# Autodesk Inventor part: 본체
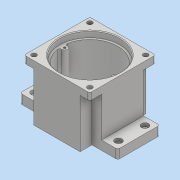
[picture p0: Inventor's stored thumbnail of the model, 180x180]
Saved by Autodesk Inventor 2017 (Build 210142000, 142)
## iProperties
Part Number: 본체
Material: 일반
Document SubType Name: Modeling
Designer: user
Density: 1 g/cm^3
Appearance: 기본값
Author: user
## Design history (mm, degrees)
sketch "스케치1"
  geometry: L1 (-70, -30)-(70, -30); L2 (70, -30)-(70, 30); L3 (70, 30)-(-70, 30); L4 (-70, 30)-(-70, -30); L5 (-70, -30)-(70, 30); L6 (70, -30)-(-70, 30); L7 (-33, -47)-(33, -47); L8 (33, -47)-(33, 47); L9 (33, 47)-(-33, 47); L10 (-33, 47)-(-33, -47); L11 (-33, -47)-(33, 47); L12 (33, -47)-(-33, 47); 1 further point
  constraints: 24 end point, 4 midpoint, 4 parallel, 2 horizontal, 2 perpendicular
  dimensions: "d0" = 66 distance of L8.end L9.end; "d1" = 60 distance of L1.end L2.end; "d2" = 140 distance of L1.start L1.end; "d3" = 94 distance between parallel lines of L9 L7
extrude "돌출1" new body sketch "스케치1" distance "d4" = 13; taper "d5" = 0 deg
sketch "스케치2"
  geometry: L1 (-33, 47)-(33, 47); L2 (33, 47)-(33, -47); L3 (33, -47)-(-33, -47); L4 (-33, -47)-(-33, 47); L5 (-33, 47)-(33, -47); L6 (33, 47)-(-33, -47); L7 (-47, -30)-(47, -30); L8 (47, -30)-(47, 30); L9 (47, 30)-(-47, 30); L10 (-47, 30)-(-47, -30); L11 (-47, -30)-(47, 30); L12 (47, -30)-(-47, 30); 3 further points
  constraints: 24 end point, 5 midpoint, 4 parallel, 2 horizontal, 2 perpendicular, 1 coincident
  dimensions: "d6" = 66 distance of L1.start L1.end; "d7" = 94 distance of L1.end L2.end; "d8" = 94 distance of L8.end L9.end; "d9" = 60 distance of L7.end L8.end
extrude "돌출2" join sketch "스케치2" distance "d10" = 57; taper "d11" = 0 deg
sketch "스케치3"
  geometry: L1 (-47, -47)-(47, -47); L2 (47, -47)-(47, 47); L3 (47, 47)-(-47, 47); L4 (-47, 47)-(-47, -47); L5 (-47, -47)-(47, 47); L6 (47, -47)-(-47, 47); 3 further points
  constraints: 12 end point, 3 midpoint, 2 parallel, 1 coincident, 1 horizontal, 1 perpendicular
  dimensions: "d12" = 94 distance of L2.end L3.end; "d13" = 94 distance of L1.end L2.end
extrude "돌출3" join sketch "스케치3" distance "d14" = 10; taper "d15" = 0 deg
sketch "스케치4"
  geometry: L1 (-40, -40)-(40, -40); L2 (40, -40)-(40, 40); L3 (40, 40)-(-40, 40); L4 (-40, 40)-(-40, -40); L5 (-40, -40)-(40, 40); L6 (40, -40)-(-40, 40); C1 r 3.5 at (40, 40); C2 r 3.5 at (-40, 40); C3 r 3.5 at (-40, -40); C4 r 3.5 at (40, -40); 1 further point
  constraints: 12 end point, 4 centre point, 3 coincident, 2 midpoint, 2 parallel, 1 horizontal, 1 perpendicular
  dimensions: "d16" = 80 distance of L2.end L3.end; "d17" = 80 distance of L1.end L2.end; "d18" = 7 diameter of C1; "d19" = 7 diameter of C4; "d20" = 7 diameter of C3; "d21" = 7 diameter of C2
extrude "돌출4" cut sketch "스케치4" distance "d22" = 10; taper "d23" = 0 deg
sketch "스케치5"
  geometry: C1 r 43 at (0, 0); 1 further point
  constraints: 1 centre point, 1 coincident
  dimensions: "d24" = 86 diameter of C1
extrude "돌출5" cut sketch "스케치5" distance "d25" = 9; taper "d26" = 0 deg
sketch "스케치6"
  geometry: C1 r 40 at (0, 0); 1 further point
  constraints: 1 centre point, 1 coincident
  dimensions: "d27" = 80 diameter of C1
extrude "돌출6" cut sketch "스케치6" distance "d28" = 62; taper "d29" = 0 deg
sketch "스케치7"
  geometry: C1 r 21 at (0, 11); C2 r 15 at (0, -20); 1 further point
  constraints: 2 centre point
  dimensions: "d30" = 42 diameter of C1; "d31" = 30 diameter of C2; "d32" = 11 distance of point (0, 0) C1.centre; "d33" = 20 distance of C2.centre point (0, 0)
extrude "돌출7" join sketch "스케치7" distance "d34" = 7; taper "d35" = 0 deg
sketch "스케치9"
  geometry: C1 r 27.5 at (0, 11); A1 r 21 centre (0, 11) between (8.978, -7.984) and (-8.978, -7.984) reference; 1 further point
  constraints: 1 centre point, 1 coincident
  dimensions: "d36" = 55 diameter of C1
extrude "돌출8" join sketch "스케치9" distance "d37" = 7; taper "d38" = 0 deg
hole "구멍1" diameter "d41" = 25; stored, may be unused: countersink angle "d45" = 90 deg, drill point angle "d47" = 0 deg; dims "d39" = 10, "d40" = 10, "d42" = 6, "d43" = 35, "d44" = 10, "d46" = 100
hole "구멍2" diameter "d50" = 32; stored, may be unused: countersink angle "d54" = 90 deg, drill point angle "d56" = 0 deg; dims "d48" = 10, "d49" = 10, "d51" = 6, "d52" = 35, "d53" = 10, "d55" = 8.3
hole "구멍3" diameter "d59" = 19; stored, may be unused: countersink angle "d63" = 90 deg, drill point angle "d65" = 0 deg; dims "d57" = 10, "d58" = 10, "d60" = 6, "d61" = 22, "d62" = 7, "d64" = 10
chamfer "모따기1" distance "d66" = 1; stored, may be unused: second distance "d67" = 2, angle "d68" = 45 deg
chamfer "모따기2" distance "d69" = 0.8; stored, may be unused: second distance "d70" = 2, angle "d71" = 30 deg
sketch "스케치10"
  geometry: A1 r 40 centre (0, 0) between (-39.279, 7.559) and (-39.279, -7.559) reference; A2 r 4 centre (-36, 0) between (-36.19, -3.995) and (-36.19, 3.995); A3 r 3 centre (-36.333, 6.992) between (-39.279, 7.559) and (-36.19, 3.995); A4 r 3 centre (-36.333, -6.992) between (-36.19, -3.995) and (-39.279, -7.559); A5 r 40 centre (0, 0) between (-39.279, 7.559) and (-39.279, -7.559); 1 further point
  constraints: 10 point on circle, 6 tangent, 4 centre point, 1 horizontal alignment
  dimensions: "d72" = 8 diameter of A2; "d73" = 36 distance of A2.centre point (0, 0); "d74" = 3 radius of A3; "d75" = 3 radius of A4
extrude "돌출9" join sketch "스케치10" stored distance "d76" = 7; taper "d77" = 0 deg
hole "구멍4" diameter "d80" = 3.242; stored, may be unused: countersink angle "d84" = 90 deg, drill point angle "d86" = 118 deg; dims "d78" = 10, "d79" = 10, "d81" = 7, "d82" = 22, "d83" = 7, "d85" = 9
fillet "모깎기1" dims "d87" = 3
sketch "스케치11"
  geometry: L1 (77, -80)-(-11, -80) reference; L2 (66, 0)-(0, 0) reference; 3 further points
  constraints: 1 midpoint, 1 vertical alignment, 1 other
  dimensions: "d88" = 40 distance from line of L1 point (33, -40)
feature "엠보싱1" sketch "스케치11" dims "d1" = 60, "d2" = 140, "d6" = 66, "d7" = 94, "d8" = 94, "d9" = 60, "d89" = 0.5, "d90" = 0
sketch "스케치12"
  geometry: 3 further points
  constraints: 1 vertical alignment
  dimensions: "d91" = 60 horizontal distance of point (0, 0) point (-60, 19); "d92" = 38 distance of point (-60, -19) point (-60, 19); "d93" = 19 vertical distance of point (0, 0) point (-60, 19)
hole "구멍5" sketch "스케치12" at (-60, 19), (-60, -19) diameter "d94" = 4.5; stored, may be unused: countersink angle "d98" = 90 deg, drill point angle "d100" = 118 deg; dims "d95" = 7, "d96" = 10, "d97" = 5, "d99" = 100
chamfer "모따기3" distance "d101" = 1; stored, may be unused: second distance "d102" = 2, angle "d103" = 30 deg
fillet "모깎기2" dims "d104" = 3
fillet "모깎기3" dims "d105" = 3
chamfer "모따기4" distance "d106" = 1; stored, may be unused: second distance "d107" = 2, angle "d108" = 30 deg
node "솔리드1"
mirror "미러1"
mirror "미러2"
